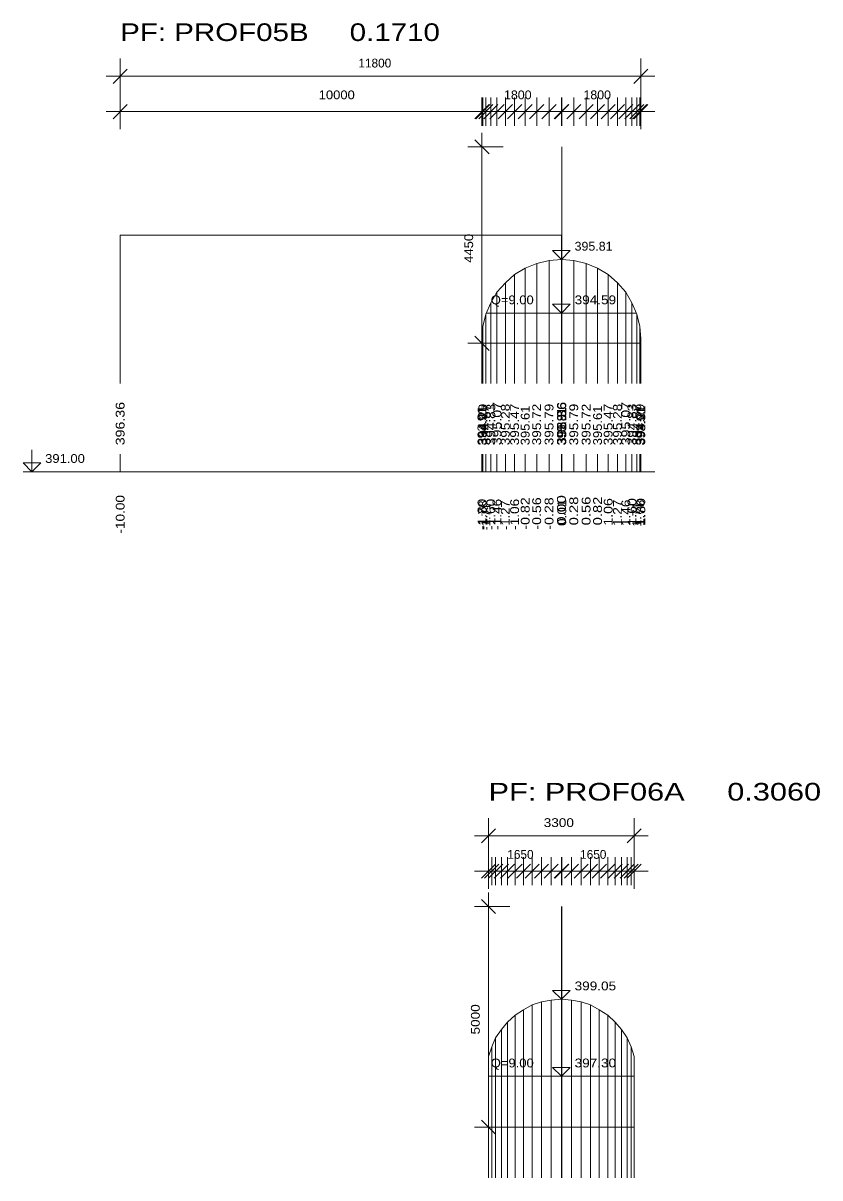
# Model space of a CAD drawing. Extents: x 7 to 442, y -393 to 441.
# Drawn here: x 289.44 to 307.49, y 43.2 to 69.37 of the extents above; entities that cross this region are included whole.
import ezdxf

# ---------------------------------------------------------------- set-up
doc = ezdxf.new("R2010")
doc.units = 0
doc.header["$LTSCALE"] = 0.08
doc.layers.add('7', color=7, linetype='Continuous', lineweight=13)

msp = doc.modelspace()

# ---------------------------------------------------------------- linework, layer by layer
at = {"layer": '7'}
for p, q in [((291.635, 66.96), (291.635, 68.56)), ((303.435, 66.96), (303.435, 68.56)), ((291.475, 68), (291.795, 68.32)), ((303.275, 68), (303.595, 68.32)), ((291.315, 68.16), (303.755, 68.16)), ((291.475, 67.2), (291.795, 67.52)), ((291.635, 67.04), (291.635, 67.68)), ((299.675, 67.2), (299.995, 67.52)), ((299.675, 67.2), (299.995, 67.52)), ((299.695, 67.2), (300.015, 67.52)), ((299.765, 67.2), (300.085, 67.52)), ((299.835, 67.04), (299.835, 67.68)), ((299.835, 67.04), (299.835, 67.68)), ((299.855, 67.04), (299.855, 67.68)), ((299.875, 67.2), (300.195, 67.52)), ((299.925, 67.04), (299.925, 67.68)), ((300.015, 67.2), (300.335, 67.52)), ((300.035, 67.04), (300.035, 67.68)), ((300.175, 67.04), (300.175, 67.68)), ((300.205, 67.2), (300.525, 67.52)), ((300.365, 67.04), (300.365, 67.68)), ((300.415, 67.2), (300.735, 67.52)), ((300.575, 67.04), (300.575, 67.68)), ((300.655, 67.2), (300.975, 67.52)), ((300.815, 67.04), (300.815, 67.68)), ((300.915, 67.2), (301.235, 67.52)), ((301.075, 67.04), (301.075, 67.68)), ((301.195, 67.2), (301.515, 67.52)), ((301.355, 67.04), (301.355, 67.68)), ((301.475, 67.2), (301.795, 67.52)), ((301.475, 67.2), (301.795, 67.52)), ((301.475, 67.2), (301.795, 67.52)), ((301.485, 67.2), (301.805, 67.52)), ((301.485, 67.2), (301.805, 67.52)), ((301.635, 67.04), (301.635, 67.68)), ((301.635, 67.04), (301.635, 67.68)), ((301.635, 67.04), (301.635, 67.68)), ((301.645, 67.04), (301.645, 67.68)), ((301.645, 67.04), (301.645, 67.68)), ((301.755, 67.2), (302.075, 67.52)), ((301.915, 67.04), (301.915, 67.68)), ((302.035, 67.2), (302.355, 67.52)), ((302.195, 67.04), (302.195, 67.68)), ((302.295, 67.2), (302.615, 67.52)), ((302.455, 67.04), (302.455, 67.68)), ((302.535, 67.2), (302.855, 67.52)), ((302.695, 67.04), (302.695, 67.68)), ((302.745, 67.2), (303.065, 67.52)), ((302.905, 67.04), (302.905, 67.68)), ((302.935, 67.2), (303.255, 67.52)), ((303.075, 67.2), (303.395, 67.52)), ((303.095, 67.04), (303.095, 67.68)), ((303.185, 67.2), (303.505, 67.52)), ((303.235, 67.04), (303.235, 67.68)), ((303.255, 67.2), (303.575, 67.52)), ((303.275, 67.2), (303.595, 67.52)), ((303.275, 67.2), (303.595, 67.52)), ((303.345, 67.04), (303.345, 67.68)), ((303.415, 67.04), (303.415, 67.68)), ((303.435, 67.04), (303.435, 67.68)), ((303.435, 67.04), (303.435, 67.68)), ((291.315, 67.36), (303.755, 67.36)), ((299.835, 61.95), (299.835, 66.88)), ((299.515, 66.56), (300.315, 66.56)), ((299.995, 66.4), (299.675, 66.72)), ((301.645, 61.2), (301.645, 66.56)), ((291.635, 61.2), (291.635, 64.56)), ((301.635, 61.2), (301.635, 64.56)), ((301.075, 61.2), (301.075, 63.92)), ((301.355, 61.2), (301.355, 63.99)), ((301.635, 61.2), (301.635, 64.01)), ((301.635, 64.01), (301.645, 64.01)), ((301.645, 61.2), (301.645, 64.01)), ((301.915, 61.2), (301.915, 63.99)), ((302.195, 61.2), (302.195, 63.92)), ((300.575, 61.2), (300.575, 63.67)), ((300.815, 61.2), (300.815, 63.81)), ((302.455, 61.2), (302.455, 63.81)), ((302.695, 61.2), (302.695, 63.67)), ((300.365, 61.2), (300.365, 63.48)), ((302.905, 61.2), (302.905, 63.48)), ((300.175, 61.2), (300.175, 63.27)), ((303.095, 61.2), (303.095, 63.27)), ((300.035, 61.2), (300.035, 63.03)), ((303.235, 61.2), (303.235, 63.03)), ((299.925, 61.2), (299.925, 62.77)), ((299.935, 62.795), (303.335, 62.795)), ((303.345, 61.2), (303.345, 62.77)), ((299.855, 61.2), (299.855, 62.49)), ((303.415, 61.2), (303.415, 62.49)), ((299.515, 62.11), (300.315, 62.11)), ((299.995, 61.95), (299.675, 62.27)), ((299.835, 61.2), (299.835, 62.21)), ((299.835, 61.2), (299.835, 62.11)), ((301.635, 61.2), (301.635, 62.11)), ((303.435, 61.2), (303.435, 62.21)), ((303.435, 61.2), (303.435, 62.11)), ((291.635, 59.2), (291.635, 59.6)), ((299.835, 59.2), (299.835, 59.6)), ((299.835, 59.2), (299.835, 59.6)), ((299.855, 59.2), (299.855, 59.6)), ((299.925, 59.2), (299.925, 59.6)), ((300.035, 59.2), (300.035, 59.6)), ((300.175, 59.2), (300.175, 59.6)), ((300.365, 59.2), (300.365, 59.6)), ((300.575, 59.2), (300.575, 59.6)), ((300.815, 59.2), (300.815, 59.6)), ((301.075, 59.2), (301.075, 59.6)), ((301.355, 59.2), (301.355, 59.6)), ((301.635, 59.2), (301.635, 59.6)), ((301.635, 59.2), (301.635, 59.6)), ((301.635, 59.2), (301.635, 59.6)), ((301.645, 59.2), (301.645, 59.6)), ((301.645, 59.2), (301.645, 59.6)), ((301.915, 59.2), (301.915, 59.6)), ((302.195, 59.2), (302.195, 59.6)), ((302.455, 59.2), (302.455, 59.6)), ((302.695, 59.2), (302.695, 59.6)), ((302.905, 59.2), (302.905, 59.6)), ((303.095, 59.2), (303.095, 59.6)), ((303.235, 59.2), (303.235, 59.6)), ((303.345, 59.2), (303.345, 59.6)), ((303.415, 59.2), (303.415, 59.6)), ((303.435, 59.2), (303.435, 59.6)), ((303.435, 59.2), (303.435, 59.6)), ((289.435, 59.2), (303.755, 59.2)), ((299.985, 49.75), (299.985, 51.35)), ((303.285, 49.75), (303.285, 51.35)), ((299.825, 50.79), (300.145, 51.11)), ((303.125, 50.79), (303.445, 51.11)), ((299.665, 50.95), (303.605, 50.95)), ((299.825, 49.99), (300.145, 50.31)), ((299.825, 49.99), (300.145, 50.31)), ((299.895, 49.99), (300.215, 50.31)), ((299.985, 49.83), (299.985, 50.47)), ((299.985, 49.83), (299.985, 50.47)), ((299.985, 49.99), (300.305, 50.31)), ((300.055, 49.83), (300.055, 50.47)), ((300.115, 49.99), (300.435, 50.31)), ((300.145, 49.83), (300.145, 50.47)), ((300.255, 49.99), (300.575, 50.31)), ((300.275, 49.83), (300.275, 50.47)), ((300.415, 49.83), (300.415, 50.47)), ((300.425, 49.99), (300.745, 50.31)), ((300.585, 49.83), (300.585, 50.47)), ((300.615, 49.99), (300.935, 50.31)), ((300.775, 49.83), (300.775, 50.47)), ((300.815, 49.99), (301.135, 50.31)), ((300.975, 49.83), (300.975, 50.47)), ((301.025, 49.99), (301.345, 50.31)), ((301.185, 49.83), (301.185, 50.47)), ((301.245, 49.99), (301.565, 50.31)), ((301.405, 49.83), (301.405, 50.47)), ((301.475, 49.99), (301.795, 50.31)), ((301.475, 49.99), (301.795, 50.31)), ((301.475, 49.99), (301.795, 50.31)), ((301.485, 49.99), (301.805, 50.31)), ((301.485, 49.99), (301.805, 50.31)), ((301.635, 49.83), (301.635, 50.47)), ((301.635, 49.83), (301.635, 50.47)), ((301.635, 49.83), (301.635, 50.47)), ((301.645, 49.83), (301.645, 50.47)), ((301.645, 49.83), (301.645, 50.47)), ((301.705, 49.99), (302.025, 50.31)), ((301.865, 49.83), (301.865, 50.47)), ((301.925, 49.99), (302.245, 50.31)), ((302.085, 49.83), (302.085, 50.47)), ((302.135, 49.99), (302.455, 50.31)), ((302.295, 49.83), (302.295, 50.47)), ((302.335, 49.99), (302.655, 50.31)), ((302.495, 49.83), (302.495, 50.47)), ((302.525, 49.99), (302.845, 50.31)), ((302.685, 49.83), (302.685, 50.47)), ((302.695, 49.99), (303.015, 50.31)), ((302.835, 49.99), (303.155, 50.31)), ((302.855, 49.83), (302.855, 50.47)), ((302.965, 49.99), (303.285, 50.31)), ((302.995, 49.83), (302.995, 50.47)), ((303.055, 49.99), (303.375, 50.31)), ((303.125, 49.83), (303.125, 50.47)), ((303.125, 49.99), (303.445, 50.31)), ((303.125, 49.99), (303.445, 50.31)), ((303.215, 49.83), (303.215, 50.47)), ((303.285, 49.83), (303.285, 50.47)), ((303.285, 49.83), (303.285, 50.47)), ((299.665, 50.15), (303.605, 50.15)), ((300.145, 49.19), (299.825, 49.51)), ((299.985, 44.19), (299.985, 49.67)), ((299.665, 49.35), (300.465, 49.35)), ((301.635, 43.2), (301.635, 49.35)), ((301.645, 43.2), (301.645, 49.35)), ((300.975, 43.2), (300.975, 47.12)), ((301.185, 43.2), (301.185, 47.19)), ((301.405, 43.2), (301.405, 47.23)), ((301.635, 43.2), (301.635, 47.25)), ((301.635, 47.25), (301.645, 47.25)), ((301.645, 43.2), (301.645, 47.25)), ((301.865, 43.2), (301.865, 47.23)), ((302.085, 43.2), (302.085, 47.19)), ((302.295, 43.2), (302.295, 47.12)), ((300.585, 43.2), (300.585, 46.89)), ((300.775, 43.2), (300.775, 47.01)), ((302.495, 43.2), (302.495, 47.01)), ((302.685, 43.2), (302.685, 46.89)), ((300.415, 43.2), (300.415, 46.73)), ((302.855, 43.2), (302.855, 46.73)), ((300.145, 43.2), (300.145, 46.37)), ((300.275, 43.2), (300.275, 46.56)), ((302.995, 43.2), (302.995, 46.56)), ((303.125, 43.2), (303.125, 46.37)), ((300.055, 43.2), (300.055, 46.17)), ((303.215, 43.2), (303.215, 46.17)), ((299.985, 43.2), (299.985, 45.95)), ((303.285, 43.2), (303.285, 45.95)), ((299.985, 45.504), (303.285, 45.504)), ((300.145, 44.19), (299.825, 44.51)), ((299.665, 44.35), (300.465, 44.35)), ((299.985, 43.2), (299.985, 44.35)), ((301.635, 43.2), (301.635, 44.35)), ((303.285, 43.2), (303.285, 44.35))]:
    msp.add_line(p, q, dxfattribs=at)
for points in [[(291.635, 64.56), (301.635, 64.56), (301.635, 64.01), (301.355, 63.99), (301.075, 63.92), (300.815, 63.81), (300.575, 63.67), (300.365, 63.48), (300.175, 63.27), (300.035, 63.03), (299.925, 62.77), (299.855, 62.49), (299.835, 62.21), (299.835, 62.11), (301.635, 62.11), (303.435, 62.11), (303.435, 62.21), (303.415, 62.49), (303.345, 62.77), (303.235, 63.03), (303.095, 63.27), (302.905, 63.48), (302.695, 63.67), (302.455, 63.81), (302.195, 63.92), (301.915, 63.99), (301.645, 64.01), (301.645, 66.56)], [(301.635, 64.51), (301.635, 64.01), (301.435, 64.21), (301.835, 64.21), (301.635, 64.01)], [(301.635, 63.295), (301.635, 62.795), (301.435, 62.995), (301.835, 62.995), (301.635, 62.795)], [(289.635, 59.7), (289.635, 59.2), (289.435, 59.4), (289.835, 59.4), (289.635, 59.2)], [(301.635, 49.35), (301.635, 47.25), (301.405, 47.23), (301.185, 47.19), (300.975, 47.12), (300.775, 47.01), (300.585, 46.89), (300.415, 46.73), (300.275, 46.56), (300.145, 46.37), (300.055, 46.17), (299.985, 45.95), (299.985, 44.35), (301.635, 44.35), (303.285, 44.35), (303.285, 45.95), (303.215, 46.17), (303.125, 46.37), (302.995, 46.56), (302.855, 46.73), (302.685, 46.89), (302.495, 47.01), (302.295, 47.12), (302.085, 47.19), (301.865, 47.23), (301.645, 47.25), (301.645, 49.35)], [(301.635, 47.75), (301.635, 47.25), (301.435, 47.45), (301.835, 47.45), (301.635, 47.25)], [(301.635, 46.004), (301.635, 45.504), (301.435, 45.704), (301.835, 45.704), (301.635, 45.504)]]:
    msp.add_lwpolyline(points, dxfattribs=at)

# ---------------------------------------------------------------- texts
for s, height, width, p in [('PF: PROF05B     0.1710', 0.4, 1.25, (291.635, 68.96)), ('10000', 0.2, 1.1, (296.135, 67.64)), ('1800', 0.2, 1.05, (300.335, 67.64)), ('1800', 0.2, 1.05, (302.135, 67.64)), ('395.81', 0.2, 1.05, (301.935, 64.21)), ('Q=9.00', 0.2, 1.1, (300.035, 62.995)), ('394.59', 0.2, 1.15, (301.935, 62.995)), ('391.00', 0.2, 1.1, (289.935, 59.4)), ('PF: PROF06A     0.3060', 0.4, 1.3, (299.985, 51.75)), ('3300', 0.2, 1.15, (301.235, 51.15)), ('399.05', 0.2, 1.15, (301.935, 47.45)), ('Q=9.00', 0.2, 1.1, (300.035, 45.704)), ('397.30', 0.2, 1.15, (301.935, 45.704))]:
    msp.add_text(s, height=height, dxfattribs=dict(at, width=width)).set_placement(p)
for s, p in [('11800', (297.035, 68.36)), ('1650', (300.41, 50.43)), ('1650', (302.06, 50.43))]:
    msp.add_text(s, height=0.2, dxfattribs=at).set_placement(p)
for s, width, p in [('4450', 1.1, (299.635, 63.935)), ('396.36 ', 1.2, (291.735, 59.8)), ('394.29 ', 1.15, (299.955, 59.8)), ('394.57 ', 1.15, (300.025, 59.8)), ('394.83 ', 1.15, (300.135, 59.8)), ('395.07 ', 1.2, (300.275, 59.8)), ('395.28 ', 1.15, (300.465, 59.8)), ('395.47 ', 1.15, (300.675, 59.8)), ('395.72 ', 1.15, (301.175, 59.8)), ('395.79 ', 1.15, (301.455, 59.8)), ('396.36 ', 1.2, (301.735, 59.8)), ('398.36 ', 1.2, (301.745, 59.8)), ('395.79 ', 1.15, (302.015, 59.8)), ('395.72 ', 1.15, (302.295, 59.8)), ('395.47 ', 1.15, (302.795, 59.8)), ('395.28 ', 1.15, (303.005, 59.8)), ('395.07 ', 1.2, (303.195, 59.8)), ('394.83 ', 1.15, (303.335, 59.8)), ('394.57 ', 1.15, (303.445, 59.8)), ('394.29 ', 1.15, (303.515, 59.8)), ('394.01 ', 1.1, (299.935, 59.8)), ('393.91 ', 1.05, (299.935, 59.8)), ('395.61 ', 1.1, (300.915, 59.8)), ('395.81 ', 1.05, (301.735, 59.8)), ('393.91 ', 1.05, (301.735, 59.8)), ('395.81 ', 1.05, (301.745, 59.8)), ('395.61 ', 1.1, (302.555, 59.8)), ('394.01 ', 1.1, (303.535, 59.8)), ('393.91 ', 1.05, (303.535, 59.8)), ('-10.00 ', 1.15, (291.735, 57.8)), ('  0.00 ', 1.3, (301.735, 57.8)), ('  0.00 ', 1.3, (301.735, 57.8)), ('  0.00 ', 1.3, (301.735, 57.8)), ('  0.28 ', 1.25, (302.015, 57.8)), ('  0.56 ', 1.25, (302.295, 57.8)), ('  0.82 ', 1.25, (302.555, 57.8)), (' -1.80 ', 1.15, (299.935, 57.8)), (' -1.80 ', 1.15, (299.935, 57.8)), (' -1.78 ', 1.1, (299.955, 57.8)), (' -1.60 ', 1.15, (300.135, 57.8)), (' -1.46 ', 1.15, (300.275, 57.8)), (' -1.27 ', 1.1, (300.465, 57.8)), (' -1.06 ', 1.15, (300.675, 57.8)), (' -0.82 ', 1.2, (300.915, 57.8)), (' -0.56 ', 1.2, (301.175, 57.8)), (' -0.28 ', 1.2, (301.455, 57.8)), ('  0.01 ', 1.15, (301.745, 57.8)), ('  0.01 ', 1.15, (301.745, 57.8)), ('  1.06 ', 1.2, (302.795, 57.8)), ('  1.27 ', 1.15, (303.005, 57.8)), ('  1.46 ', 1.15, (303.195, 57.8)), ('  1.60 ', 1.2, (303.335, 57.8)), ('  1.71 ', 1.05, (303.445, 57.8)), ('  1.78 ', 1.15, (303.515, 57.8)), ('  1.80 ', 1.2, (303.535, 57.8)), ('  1.80 ', 1.2, (303.535, 57.8)), ('5000', 1.15, (299.785, 46.45))]:
    msp.add_text(s, height=0.2, rotation=90, dxfattribs=dict(at, width=width)).set_placement(p)
msp.add_text(' -1.71 ', height=0.2, rotation=90, dxfattribs=at).set_placement((300.025, 57.8))

doc.saveas('drawing.dxf')
